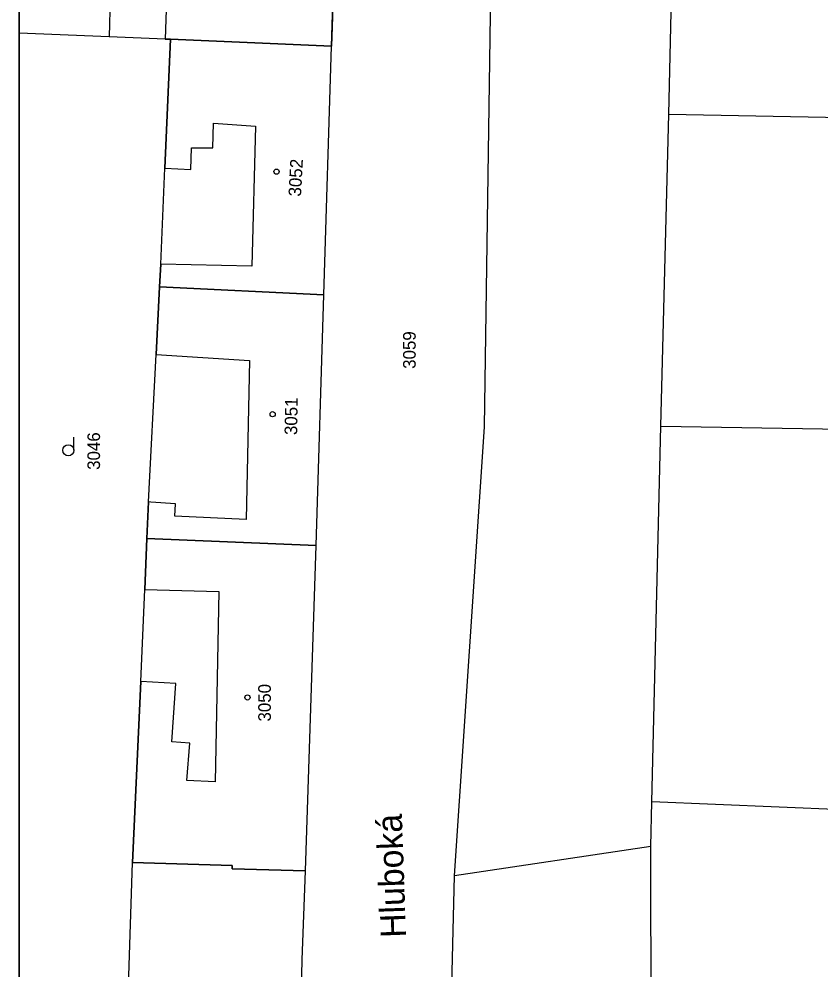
# Model space of a CAD drawing. Extents: x -534410 to -534262, y -1190162 to -1189584.
# Drawn here: x -534410.1 to -534356.1, y -1190081.7 to -1190017.6 of the extents above; entities that cross this region are included whole.
import ezdxf

# ---------------------------------------------------------------- set-up
doc = ezdxf.new("R2010")
doc.units = 0
for name, color, linetype in [('_rámeček', 7, 'Continuous'), ('_rámeček_mřížka', 7, 'Continuous'), ('Hranice parcel', 7, 'Continuous'), ('Parcelní čísla', 7, 'Continuous'), ('Polygon budovy', 7, 'Continuous'), ('Pop  PČ popisy', 7, 'Continuous'), ('Značky budov', 7, 'Continuous'), ('Značky kultur', 7, 'Continuous')]:
    doc.layers.add(name, color=color, linetype=linetype)

msp = doc.modelspace()

# ---------------------------------------------------------------- linework, layer by layer
at = {"layer": '_rámeček'}
msp.add_line((-534410.126, -1189584.47), (-534410.126, -1190161.97), dxfattribs=at)
msp.add_lwpolyline([(-534410.126, -1190004.47), (-534261.626, -1190004.47), (-534261.626, -1190109.47), (-534410.126, -1190109.47)], close=True, dxfattribs=at)
at = {"layer": '_rámeček_mřížka'}
msp.add_line((-534410.126, -1189584.47), (-534410.126, -1190161.97), dxfattribs=at)
at = {"layer": 'Hranice parcel'}
for p, q in [((-534366.35, -1190024.04), (-534365.84, -1190003.05)), ((-534403.8, -1190008.85), (-534404.06, -1190018.82)), ((-534388.75, -1190009.46), (-534389.06, -1190019.44)), ((-534404.06, -1190018.82), (-534410.126, -1190018.573)), ((-534389.06, -1190019.44), (-534399.91, -1190018.99)), ((-534389.59, -1190036.21), (-534389.06, -1190019.44)), ((-534366.87, -1190045.04), (-534366.35, -1190024.04)), ((-534366.35, -1190024.04), (-534342.06, -1190024.47)), ((-534389.59, -1190036.21), (-534400.65, -1190035.66)), ((-534390.11, -1190053.08), (-534389.59, -1190036.21)), ((-534367.49, -1190070.35), (-534366.87, -1190045.04)), ((-534366.87, -1190045.04), (-534342.19, -1190045.44)), ((-534390.11, -1190053.08), (-534401.52, -1190052.62)), ((-534390.83, -1190074.99), (-534390.11, -1190053.08)), ((-534367.56, -1190073.35), (-534367.49, -1190070.35)), ((-534342.37, -1190071.42), (-534367.49, -1190070.35)), ((-534367.56, -1190073.35), (-534380.79, -1190075.34))]:
    msp.add_line(p, q, dxfattribs=at)
for points in [[(-534380.79, -1190075.34), (-534378.76, -1190045.09), (-534377.74, -1189975.71)], [(-534399.91, -1190018.99), (-534400.27, -1190018.98), (-534404.06, -1190018.82)], [(-534400.65, -1190035.66), (-534400.58, -1190034.14), (-534400.29, -1190027.66), (-534399.91, -1190018.99)], [(-534401.52, -1190052.62), (-534401.39, -1190050.15), (-534400.88, -1190040.21), (-534400.65, -1190035.66)], [(-534402.48, -1190074.44), (-534401.92, -1190062.24), (-534401.64, -1190056.04), (-534401.52, -1190052.62)], [(-534367.47, -1190102.26), (-534367.55, -1190076.15), (-534367.56, -1190073.35)], [(-534402.81, -1190084.96), (-534402.74, -1190082.76), (-534402.48, -1190074.44)], [(-534390.83, -1190074.99), (-534395.76, -1190074.86), (-534395.76, -1190074.64), (-534402.48, -1190074.44)], [(-534391.6, -1190100.55), (-534391.1, -1190082.99), (-534391.04, -1190081), (-534390.83, -1190074.99)], [(-534381.06, -1190105.11), (-534381.43, -1190102.09), (-534380.79, -1190075.34)]]:
    msp.add_lwpolyline(points, dxfattribs=at)
at = {"layer": 'Polygon budovy'}
for points in [[(-534399.91, -1190018.99), (-534389.06, -1190019.44), (-534388.75, -1190009.46), (-534399.94, -1190009.01), (-534400.27, -1190018.98)], [(-534400.58, -1190034.14), (-534400.65, -1190035.66), (-534389.59, -1190036.21), (-534389.06, -1190019.44), (-534399.91, -1190018.99), (-534400.29, -1190027.66), (-534398.55, -1190027.75), (-534398.5, -1190026.29), (-534397.07, -1190026.31), (-534397.03, -1190024.64), (-534394.19, -1190024.84), (-534394.44, -1190034.26)], [(-534400.88, -1190040.21), (-534394.59, -1190040.63), (-534394.82, -1190051.34), (-534399.63, -1190051.12), (-534399.58, -1190050.27), (-534401.24, -1190050.16), (-534401.39, -1190050.15), (-534401.52, -1190052.62), (-534390.11, -1190053.08), (-534389.59, -1190036.21), (-534400.65, -1190035.66)], [(-534399.83, -1190066.32), (-534399.57, -1190062.39), (-534401.92, -1190062.24), (-534402.48, -1190074.44), (-534395.76, -1190074.64), (-534395.76, -1190074.86), (-534390.83, -1190074.99), (-534390.11, -1190053.08), (-534401.52, -1190052.62), (-534401.64, -1190056.04), (-534396.67, -1190056.19), (-534396.91, -1190069), (-534398.81, -1190068.92), (-534398.62, -1190066.41)]]:
    msp.add_lwpolyline(points, close=True, dxfattribs=at)
at = {"layer": 'Značky budov'}
for centre in [(-534392.773, -1190027.903), (-534393.037, -1190044.241), (-534394.734, -1190063.321)]:
    msp.add_circle(centre, 0.175, dxfattribs=at)
at = {"layer": 'Značky kultur'}
msp.add_line((-534406.424, -1190046.669), (-534406.424, -1190045.794), dxfattribs=at)
msp.add_circle((-534406.799, -1190046.669), 0.375, dxfattribs=at)

# ---------------------------------------------------------------- texts
at = {"layer": 'Parcelní čísla'}
for s, rotation, p in [('3052', 87, (-534391.126, -1190029.594)), ('3059', 90, (-534383.398, -1190041.184)), ('3051', 89, (-534391.387, -1190045.652)), ('3046', 90, (-534404.667, -1190047.989)), ('3050', 90, (-534393.157, -1190064.941))]:
    msp.add_text(s, height=0.85, rotation=rotation, dxfattribs=at).set_placement(p)
at = {"layer": 'Pop  PČ popisy'}
msp.add_text('Hluboká', height=1.7, rotation=92, dxfattribs=at).set_placement((-534384.045, -1190079.482))

doc.saveas('drawing.dxf')
